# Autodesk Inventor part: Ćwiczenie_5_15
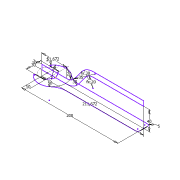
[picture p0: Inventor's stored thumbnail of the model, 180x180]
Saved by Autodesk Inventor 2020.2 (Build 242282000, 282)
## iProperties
Created: 2005-02
Part Number: Ćwiczenie_5_15
Document SubType Name: Modeling
Designer: F.Stasiak
Manufacturer: Standard
Standards Organization: Custom
Density: 1 g/cm^3
Material: Ogólny
Appearance: Domyślna
Manager: www.cadconsulting.pl
Company: Fabian Stasiak CAD Consulting
Subject: Zbiór ćwiczeń. Autodesk Inventor 2020. Kurs podstawowy
Author: F.Stasiak
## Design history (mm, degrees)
sketch "Szkic1"
  geometry: L1 (-9.672, -15)-(8.66, -15); L2 (8.66, 15)-(-9.672, 15); L3 (17.321, 0)-(8.66, 15); L4 (8.66, -15)-(17.321, 0); L5 (200, 7.5)-(200, -7.5); L6 (51.385, -12.5)-(195, -12.5); L7 (51.385, 12.5)-(195, 12.5); L8 (10, 0)-(10, -36.694); L9 (10, 0)-(10, 36.694); L10 (0, 0)-(0, -22.903); L11 (0, 0)-(-22.903, 0); L12 (0, 0)-(0, 22.903); L13 (0, 0)-(22.903, 0); L14 (28.985, 0)-(211.885, 0); C1 r 15 at (0, 0); A1 r 35 centre (51.385, -47.5) between (51.385, -12.5) and (28.394, -21.111); A2 r 28 centre (10, 0) between (-11.186, -18.308) and (28.394, -21.111); A3 r 2 centre (-9.672, 17) between (-11.186, 18.308) and (-9.672, 15); A4 r 2 centre (-9.672, -17) between (-9.672, -15) and (-11.186, -18.308); A5 r 35 centre (51.385, 47.5) between (28.394, 21.111) and (51.385, 12.5); A6 r 28 centre (10, 0) between (28.394, 21.111) and (-11.186, 18.308); A7 r 5 centre (195, 7.5) between (200, 7.5) and (195, 12.5); A8 r 5 centre (195, -7.5) between (195, -12.5) and (200, -7.5); 2 further points
  constraints: 28 end point, 16 point on circle, 16 tangent, 13 point on line, 9 centre point, 6 parallel, 3 equal radius, 1 coincident with centre, 1 horizontal, 1 midpoint, 1 vertical
  dimensions: "d1" = 10 distance of L10.start L8.start; "d3" = 35 radius of A5; "d5" = 56 diameter of A6; "d7" = 2 radius of A3; "d9" = 30 distance of L1.start L2.end; "d11" = 200 horizontal distance of L10.start L5.end; "d13" = 5 radius of A7
sketch "Szkic2"
  geometry: L1 (11.672, 10)-(11.672, 0); L2 (-95, 40)-(-200, 40); L3 (-200, 40)-(-200, 50); L4 (-95, 50)-(-200, 50); L5 (-79, 32)-(-64, 12); L6 (-71, 38)-(-56, 18); L7 (-10, -8.114)-(-10, 16.733); L8 (11.672, 10)-(-40, 10); L9 (11.672, 0)-(-40, 0); A1 r 30 centre (-40, 30) between (-64, 12) and (-40, 0); A2 r 20 centre (-40, 30) between (-56, 18) and (-40, 10); A3 r 20 centre (-95, 20) between (-79, 32) and (-95, 40); A4 r 30 centre (-95, 20) between (-71, 38) and (-95, 50); 1 further point
  constraints: 18 end point, 10 tangent, 8 point on circle, 4 centre point, 2 coincident with centre, 2 parallel, 1 horizontal, 1 vertical
  dimensions: "d14" = 10 distance of L1.start L1.end; "d15" = 20 radius of A2; "d16" = 30 radius of A1; "d17" = 20 radius of A3 (= d15); "d18" = 30 radius of A4 (= d16); "d19" = 211.67232 distance between parallel lines of L3 L1; "d20" = 40 distance between parallel lines of L2 L9; "d21" = 51.67232 distance of L1.start L8.end
node "Korpusy bryłowe"
node "Korpusy powierzchniowe"
other parameters: "d2" = 35 (derived), "d4" = 56 (derived), "d6" = 2 (derived), "d12" = 5 (derived)
